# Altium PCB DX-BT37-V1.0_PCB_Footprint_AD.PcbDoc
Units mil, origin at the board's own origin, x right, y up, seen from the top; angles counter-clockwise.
Board outline 6000 x 4000 mil, 2 copper layers (Top Layer, Bottom Layer); 1 components, 15 nets, 16 pads, 0 vias.
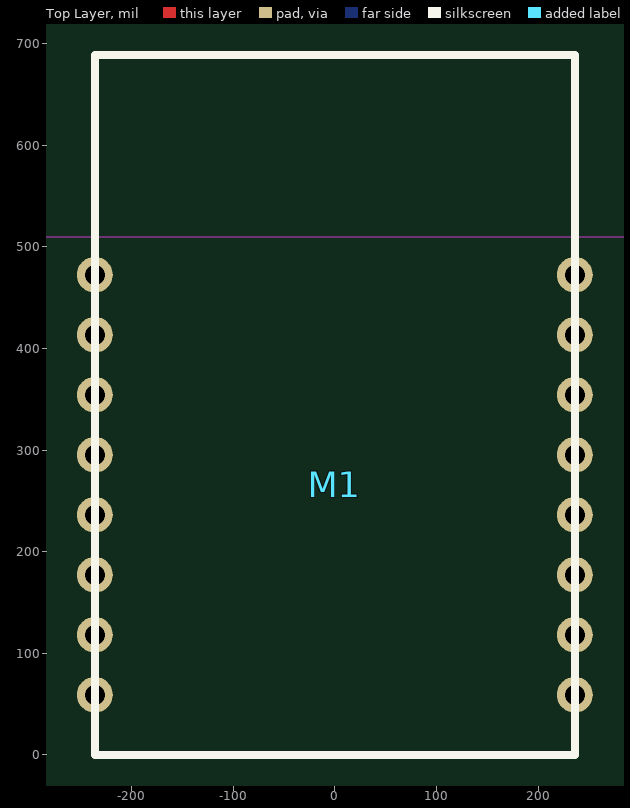
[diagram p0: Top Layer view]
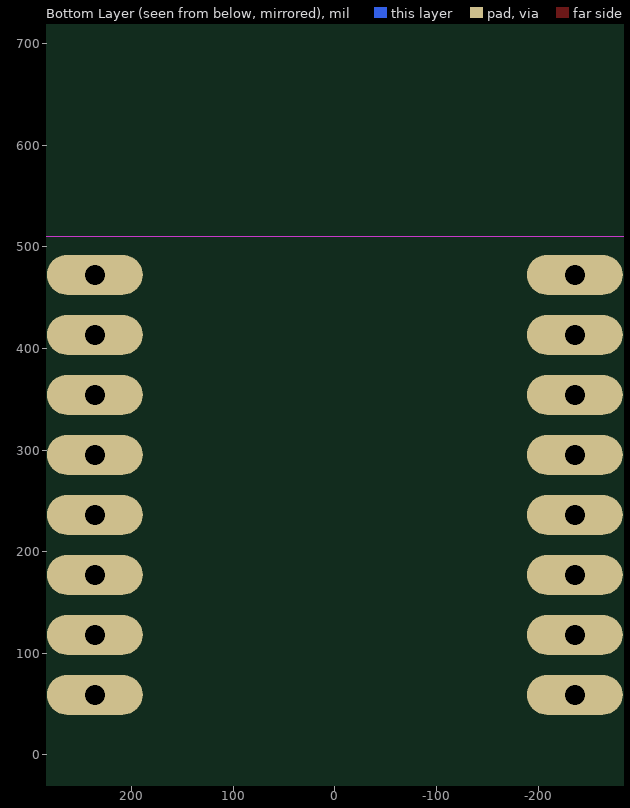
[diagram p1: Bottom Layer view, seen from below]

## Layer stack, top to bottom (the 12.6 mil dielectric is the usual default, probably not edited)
Top Solder: solder mask 0.4, Solder Resist, Dk 3.5
Top Layer: signal copper 1.4
Dielectric 1: dielectric 12.6, FR-4, Dk 4.8
Bottom Layer: signal copper 1.4
Bottom Solder: solder mask 0.4, Solder Resist, Dk 3.5

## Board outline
-2805,-1405 3195,-1405 3195,2595 -2805,2595

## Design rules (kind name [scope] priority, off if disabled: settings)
Clearance [All] p1: gap=10 ignorepadtopadclearanceinfootprint=FALSE except(0: Arc-Hole Track-Hole SMDPad-Hole THPad-Hole Via-Hole Fill-Hole Poly-Hole Region-Hole Text-Hole)
PolygonConnect [All] p1: connectstyle=Relief reliefconductorwidth=10 reliefentries=4 polygonreliefangle="90 Angle" airgapwidth=10
RoutingVias [All] p1: holewidth=28 width=50 viastyle="Through Hole" minholewidth=28 minwidth=50 maxholewidth=28 maxwidth=50
SolderMaskExpansion [All] p1: expansion=4 istentingtop=FALSE
Width [All] p1: maxlimit=10 minlimit=10 preferedwidth=10
30 further rules are at their usual default settings.

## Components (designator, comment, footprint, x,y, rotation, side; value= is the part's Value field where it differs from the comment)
M1 "DX-BT37" BT37-M 0,0 r0 top

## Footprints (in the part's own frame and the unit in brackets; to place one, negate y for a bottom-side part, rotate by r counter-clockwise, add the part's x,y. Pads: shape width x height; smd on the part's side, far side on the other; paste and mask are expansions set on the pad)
BT37-M [mm]
  round 0.9 / inner round 0.9 / far side oval 2.4x1 hole 0.5 mask-2539.97: 1(-6,12) 2(-6,10.5) 3(-6,9) 4(-6,7.5) 5(-6,6) 6(-6,4.5) 7(-6,3) 8(-6,1.5) 9(6,1.5) 10(6,3) 11(6,4.5) 12(6,6) 13(6,7.5) 14(6,9) 15(6,10.5) 16(6,12)
  Keep-Out Layer region: -7.62,12.954 7.493,12.954 7.493,18.669 -7.62,18.669
  silkscreen extent -6,0 6,17.5

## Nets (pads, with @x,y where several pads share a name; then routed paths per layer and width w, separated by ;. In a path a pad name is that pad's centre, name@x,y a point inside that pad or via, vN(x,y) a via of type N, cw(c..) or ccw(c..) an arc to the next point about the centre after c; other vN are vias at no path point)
ANT3: 
GND: 
P00/TX/D-: 
P01/RX/D+: 
P02: 
P03: 
P04: 
P05: 
P06: 
P07: 
P10: 
P11: 
P32: 
RSTN: 
VBAT: 
pads on no net: M1.1 M1.2 M1.3 M1.4 M1.5 M1.6 M1.7 M1.8 M1.9 M1.10 M1.11 M1.12 M1.13 M1.14 M1.15 M1.16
